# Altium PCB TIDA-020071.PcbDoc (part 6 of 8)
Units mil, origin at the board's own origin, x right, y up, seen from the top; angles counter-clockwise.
Board outline 5750 x 4050 mil, 6 copper layers (Top Layer, GND PLANE-1, SIGNAL LAYER, SIGNAL/POWER LAYER, GND PLANE-2, Bottom Layer), stack 59.616 mil thick; 776 components, 498 nets, 2205 pads, 871 vias.
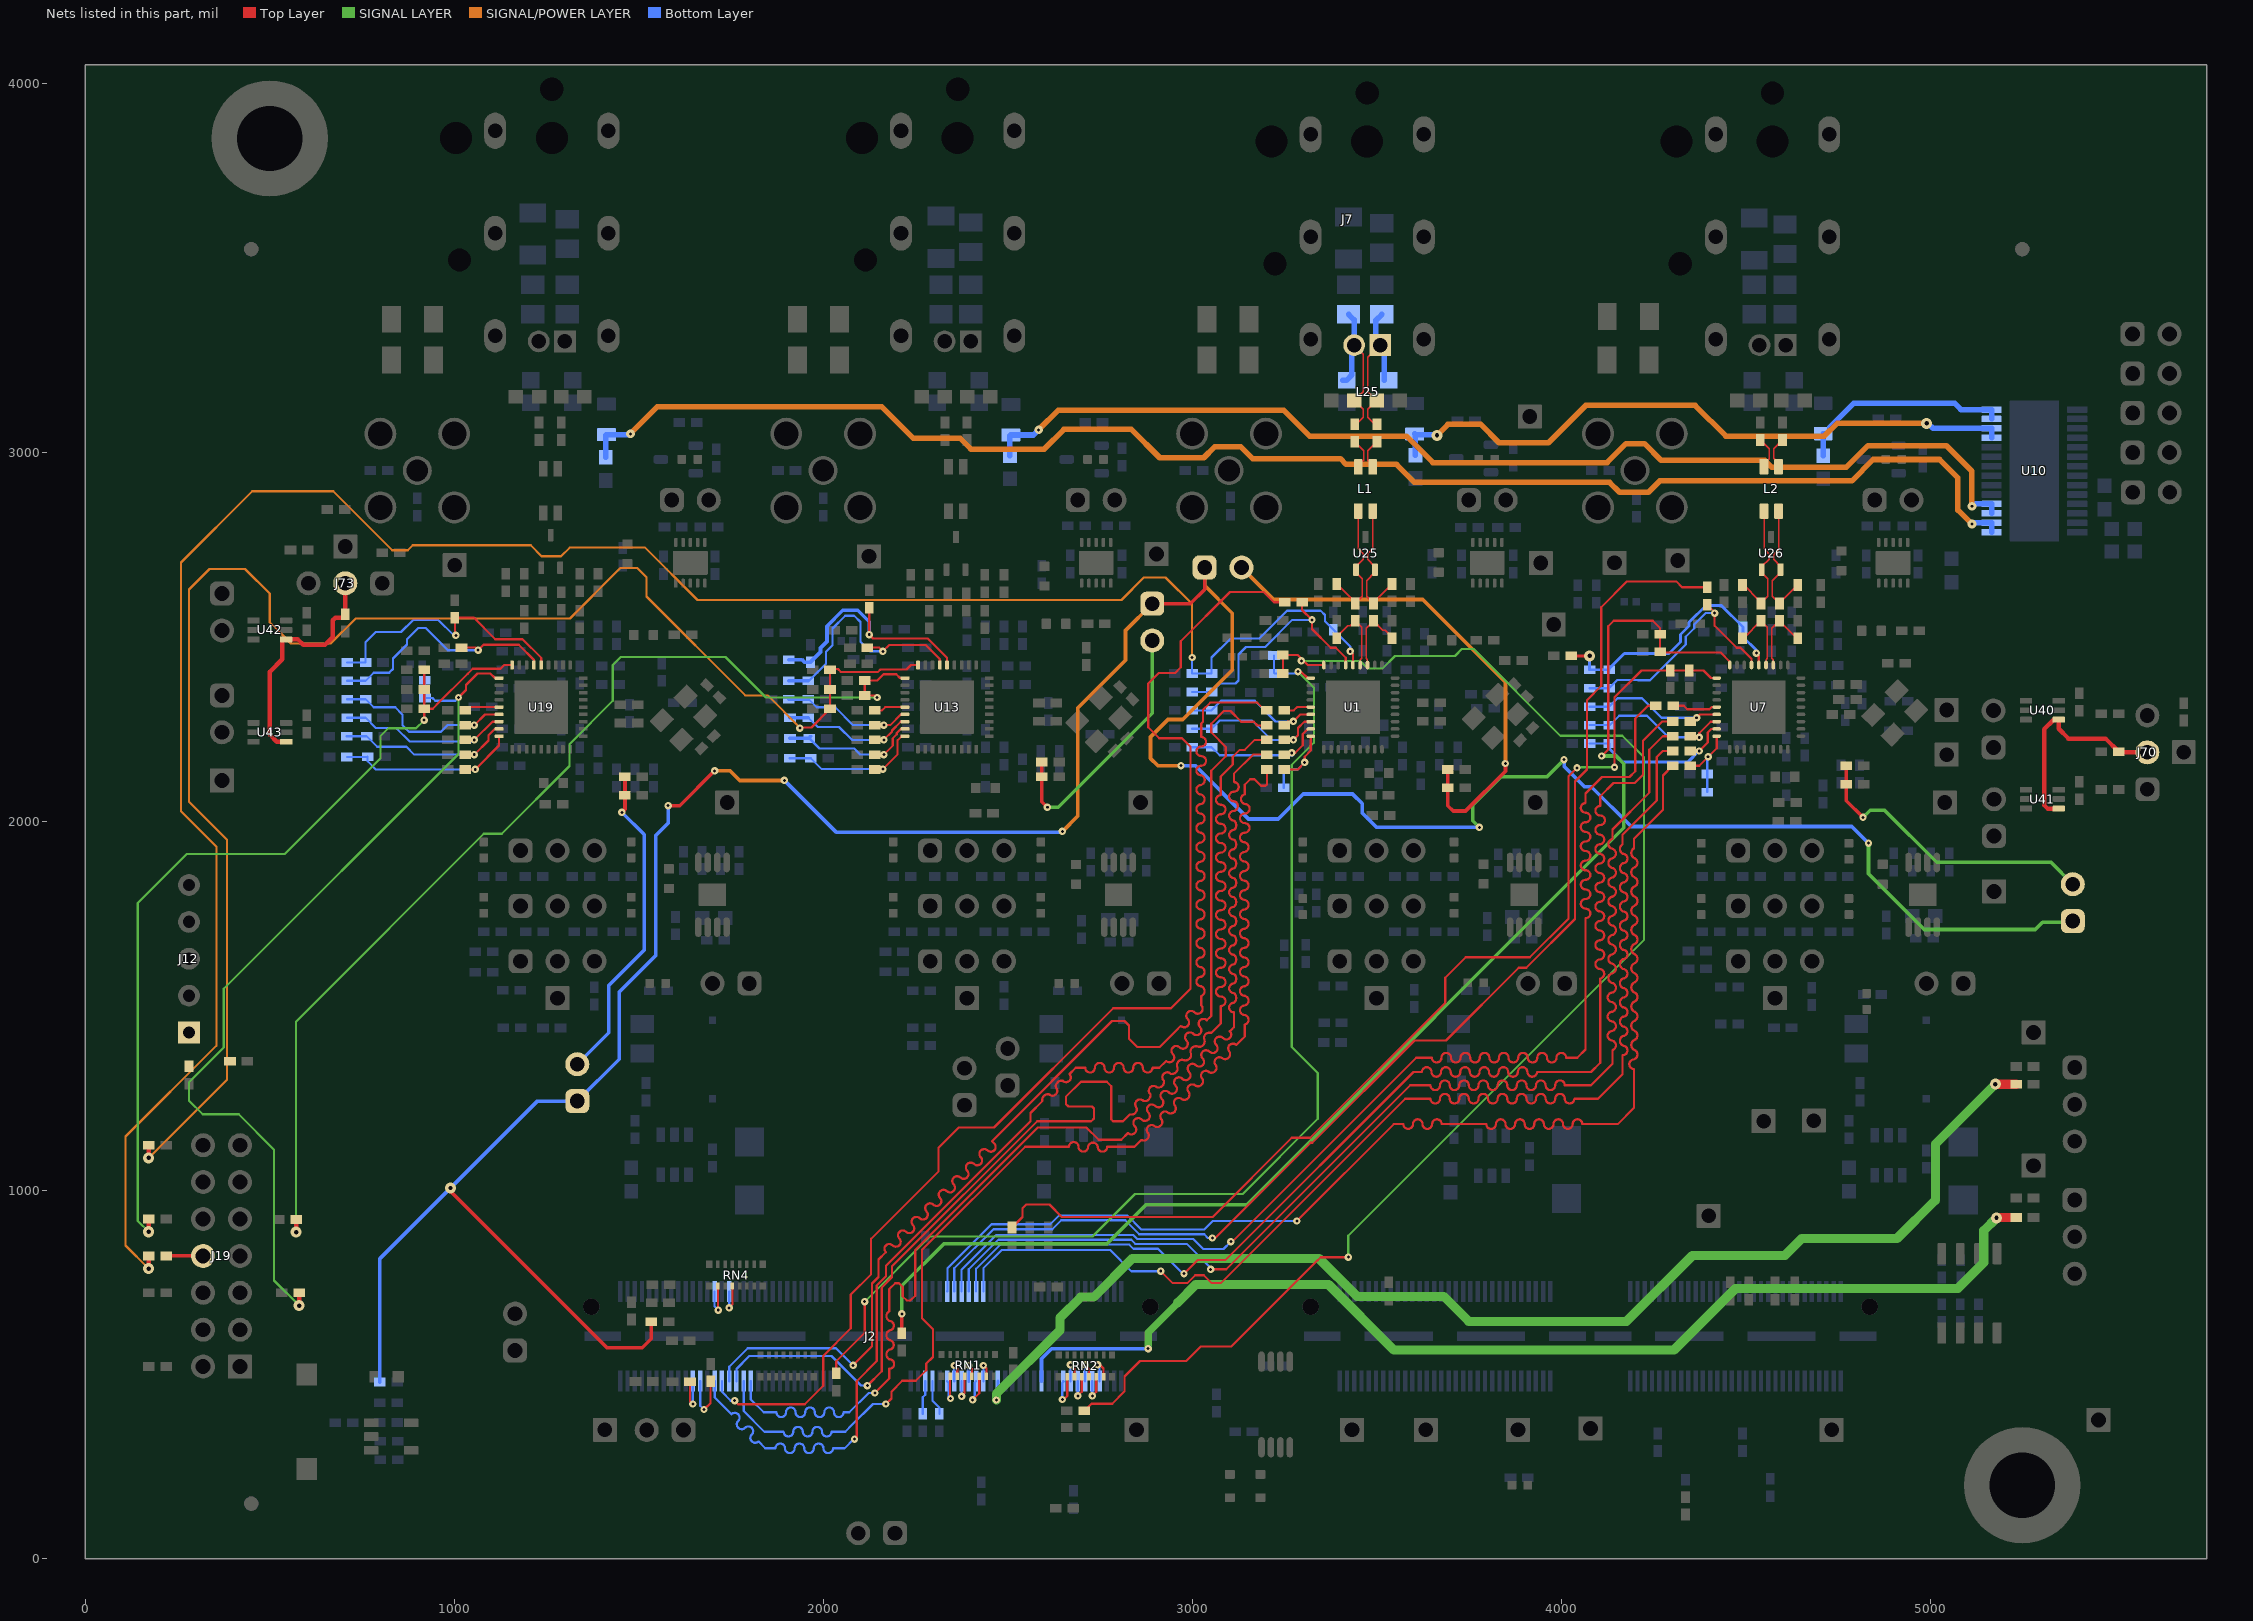
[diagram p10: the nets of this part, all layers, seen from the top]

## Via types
v1: diameter 20, hole 8, Top Layer to Bottom Layer, tented both sides, 637 vias
v2: diameter 30, hole 12, Top Layer to Bottom Layer, tented both sides, 105 vias
v3: diameter 19.68, hole 7.87, Top Layer to Bottom Layer, tented bottom, 68 vias
v4: diameter 19.68, hole 7.87, Top Layer to Bottom Layer, 25 vias
v5: diameter 24, hole 8, Top Layer to Bottom Layer, tented both sides, 24 vias
v6: diameter 19.68, hole 7.87, Top Layer to Bottom Layer, tented both sides, 12 vias

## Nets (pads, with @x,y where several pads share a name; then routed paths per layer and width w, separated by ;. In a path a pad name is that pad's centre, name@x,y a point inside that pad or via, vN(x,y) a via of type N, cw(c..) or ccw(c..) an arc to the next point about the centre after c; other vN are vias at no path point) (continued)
P0-R2-TD2: J2.89 RN4.12 | length 107.3
  Top Layer w6: v1(1745.28,680.75) 1754.01,689.48 RN4.12@1754.01,740
  Bottom Layer w6: v1(1745.28,680.75) J2.89@1745.28,725 J2.89@1745.28,725.2
P0-R2-TD3: J2.93 RN4.10 | length 120.3
  Top Layer w6: RN4.10@1714.64,740 1714.64,675.63 v1(1715.7,674.58)
  Bottom Layer w6: J2.93@1705.91,725 1705.91,684.37 v1(1715.7,674.58)
P1-R1-RCLK: J2.86 R52.2 | length 3530
  Top Layer w6: v1(2170,420) 2185,435 2185,453.4 2214.4,482.8 2250.8,482.8 2279.7,511.7 2279.7,529.7 2297.7,547.7 2297.7,622.8 2267.6,652.9 2267.6,837.34 2547.37,1117.11 2666.1,1117.11 cw(c2679.1,1117.11) 2692.1,1117.11 ccw(c2705.1,1117.11) 2718.1,1117.11 cw(c2731.1,1115.11) 2744.1,1117.11 ccw(c2757.1,1117.11) 2770.1,1117.11 2776.4,1117.11 2844.11,1117.11 2862.5,1135.49 ccw(c2868.67,1147.7) 2880.88,1153.88 cw(c2890.07,1163.07) 2899.26,1172.26 ccw(c2905.44,1184.47) 2917.65,1190.65 cw(c2926.84,1199.84) 2936.03,1209.03 ccw(c2942.21,1221.24) 2954.42,1227.42 cw(c2963.61,1236.61) 2972.8,1245.8 ccw(c2978.98,1258.01) 2991.19,1264.19 cw(c3000.38,1273.38) 3009.57,1282.57 ccw(c3015.75,1294.78) 3027.96,1300.96 cw(c3037.15,1310.15) 3046.34,1319.34 ccw(c3052.52,1331.55) 3064.73,1337.73 cw(c3073.92,1346.92) 3083.11,1356.11 ccw(c3089.29,1368.32) 3101.5,1374.5 cw(c3110.69,1383.69) 3119.88,1392.88 3135.4,1408.4 3142.7,1415.7 3142.7,1444.1 3142.7,1448.4 ccw(c3139.65,1461.4) 3142.7,1474.4 cw(c3142.7,1487.4) 3142.7,1500.4 ccw(c3139.65,1513.4) 3142.7,1526.4 cw(c3142.7,1539.4) 3142.7,1552.4 ccw(c3139.65,1565.4) 3142.7,1578.4 cw(c3142.7,1591.4) 3142.7,1604.4 ccw(c3139.65,1617.4) 3142.7,1630.4 cw(c3142.7,1643.4) 3142.7,1656.4 ccw(c3139.65,1669.4) 3142.7,1682.4 cw(c3142.7,1695.4) 3142.7,1708.4 ccw(c3139.65,1721.4) 3142.7,1734.4 cw(c3142.7,1747.4) 3142.7,1760.4 ccw(c3139.65,1773.4) 3142.7,1786.4 cw(c3142.7,1799.4) 3142.7,1812.4 ccw(c3139.65,1825.4) 3142.7,1838.4 cw(c3142.7,1851.4) 3142.7,1864.4 ccw(c3139.65,1877.4) 3142.7,1890.4 cw(c3142.7,1903.4) 3142.7,1916.4 ccw(c3139.65,1929.4) 3142.7,1942.4 cw(c3142.7,1955.4) 3142.7,1968.4 ccw(c3142.42,1981.4) 3142.7,1994.4 cw(c3142.7,2007.4) 3142.7,2020.4 ccw(c3142.7,2033.4) 3142.7,2046.4 cw(c3145.69,2059.4) 3142.7,2072.4 3142.7,2098.4 3157.5,2113.2 3169.1,2113.2 3186.8,2095.5 3199.1,2095.5 3202.76,2099.16 R52.2@3202.76,2140
  Bottom Layer w6: J2.86@1784.65,482.01 1784.65,401.15 1840.7,345.1 1866.9,345.1 1892.9,345.1 ccw(c1905.9,345.1) 1918.9,345.1 cw(c1931.9,345.1) 1944.9,345.1 ccw(c1957.9,345.1) 1970.9,345.1 cw(c1983.9,345.1) 1996.9,345.1 ccw(c2009.9,345.1) 2022.9,345.1 2048.9,345.1 2060,345.1 2078.38,363.48 2079.25,364.35 2134.9,420 v1(2170,420)
P1-R1-RCTL: J2.92 R53.2 | length 3411.1
  Top Layer w6: v1(1760,428.96) 1769.34,419.62 1950.03,419.62 2000,469.59 2000,550 2075,625 2075,716.94 2130,771.94 2130,868 2313,1051 2313,1115.11 2367.54,1169.66 2463.26,1169.66 2786.3,1492.7 2943,1492.7 2995.8,1545.5 2995.8,2201.37 2972.8,2224.36 2910.53,2224.36 2880.91,2253.98 2880.91,2372.57 2909.76,2401.42 2954.14,2401.42 2969.28,2416.56 2969.28,2487.37 3102.76,2620.85 3194.06,2620.85 3222,2592.91 R53.2@3250.76,2592.91
  Bottom Layer w6: J2.92@1725.59,482.01 1725.59,453 1749.63,428.96 v1(1760,428.96)
P1-R1-RD0: J2.84 R54.2 | length 3529.7
  Top Layer w6: v1(2140,450) 2179.4,489.4 2179.4,515.4 ccw(c2179.4,528.4) 2179.4,541.4 cw(c2186.24,554.4) 2179.4,567.4 ccw(c2178.25,580.4) 2179.4,593.4 cw(c2186.24,606.4) 2179.4,619.4 ccw(c2178.7,632.4) 2179.4,645.4 cw(c2186.24,658.4) 2179.4,671.4 2179.4,690.7 2179.4,731.5 2195.1,747.2 2205.7,747.2 2215.96,736.94 2215.96,711.14 2226.2,700.9 2236.8,700.9 2249.34,713.43 2249.34,837.46 2581.53,1169.66 2713.14,1169.66 2746.7,1136.1 2807.9,1136.1 2826.28,1154.48 ccw(c2835.48,1163.68) 2844.67,1172.87 cw(c2853.86,1182.06) 2863.05,1191.25 ccw(c2872.25,1200.45) 2881.44,1209.64 cw(c2890.63,1218.83) 2899.82,1228.02 ccw(c2909.02,1237.22) 2918.21,1246.41 cw(c2927.4,1255.6) 2936.59,1264.79 ccw(c2945.79,1273.99) 2954.98,1283.18 cw(c2964.17,1292.37) 2973.36,1301.56 ccw(c2982.56,1310.75) 2991.75,1319.95 cw(c3000.94,1329.14) 3010.13,1338.33 ccw(c3019.32,1347.52) 3028.52,1356.72 cw(c3037.71,1365.91) 3046.9,1375.1 ccw(c3056.09,1384.29) 3065.29,1393.49 cw(c3074.48,1402.68) 3083.67,1411.87 ccw(c3092.86,1421.06) 3102.06,1430.26 3107.05,1435.25 3113.2,1441.4 3113.2,1481.6 cw(c3113.2,1494.6) 3113.2,1507.6 ccw(c3103.45,1520.6) 3113.2,1533.6 cw(c3113.2,1546.6) 3113.2,1559.6 ccw(c3103.45,1572.6) 3113.2,1585.6 cw(c3113.2,1598.6) 3113.2,1611.6 ccw(c3103.45,1624.6) 3113.2,1637.6 cw(c3113.2,1650.6) 3113.2,1663.6 ccw(c3103.45,1676.6) 3113.2,1689.6 cw(c3113.2,1702.6) 3113.2,1715.6 ccw(c3103.45,1728.6) 3113.2,1741.6 cw(c3113.2,1754.6) 3113.2,1767.6 ccw(c3103.45,1780.6) 3113.2,1793.6 cw(c3113.2,1806.6) 3113.2,1819.6 ccw(c3103.45,1832.6) 3113.2,1845.6 cw(c3113.2,1858.6) 3113.2,1871.6 ccw(c3103.45,1884.6) 3113.2,1897.6 cw(c3113.2,1910.6) 3113.2,1923.6 ccw(c3103.45,1936.6) 3113.2,1949.6 cw(c3113.2,1962.6) 3113.2,1975.6 ccw(c3103.45,1988.6) 3113.2,2001.6 cw(c3113.2,2014.6) 3113.2,2027.6 ccw(c3110.91,2040.6) 3113.2,2053.6 cw(c3113.2,2066.6) 3113.2,2079.6 ccw(c3113.2,2092.6) 3113.2,2105.6 3113.2,2121.7 3113.2,2128.4 3164.8,2180 R54.2@3202.76,2180
  Bottom Layer w6: J2.84@1804.33,482.01 1804.02,481.69 1804.02,432.43 1838.75,397.7 1847.3,397.7 1873.3,397.7 ccw(c1886.3,397.7) 1899.3,397.7 cw(c1912.3,397.7) 1925.3,397.7 ccw(c1938.3,397.7) 1951.3,397.7 cw(c1964.3,397.7) 1977.3,397.7 ccw(c1990.3,397.7) 2003.3,397.7 cw(c2016.3,397.7) 2029.3,397.7 ccw(c2042.3,397.7) 2055.3,397.7 2071.1,397.7 2123.4,450 v1(2140,450)
P1-R1-RD1: J2.88 R55.2 | length 3536.2
  Top Layer w6: v1(2120,470) 2158.55,508.55 2158.55,735.91 2186.74,764.1 2186.74,793.25 2580,1186.51 2726.31,1186.51 2733.9,1194.1 2733.9,1221 2728.8,1226.1 2664.78,1226.1 2657.8,1233.08 2657.8,1252.7 2698.8,1293.7 2768.4,1293.7 2780.7,1281.4 2780.7,1191.6 2785.79,1186.51 2812.81,1186.51 2831.2,1204.9 ccw(c2835.34,1219.14) 2849.58,1223.28 cw(c2858.78,1232.48) 2867.97,1241.67 ccw(c2872.11,1255.91) 2886.35,1260.05 cw(c2895.55,1269.24) 2904.74,1278.44 ccw(c2908.88,1292.68) 2923.12,1296.82 cw(c2932.32,1306.01) 2941.51,1315.21 ccw(c2945.65,1329.45) 2959.89,1333.59 cw(c2973.06,1338.81) 2978.28,1351.98 ccw(c2982.42,1366.22) 2996.66,1370.36 cw(c3009.83,1375.58) 3015.05,1388.75 ccw(c3019.19,1402.99) 3033.43,1407.13 cw(c3046.6,1412.35) 3051.82,1425.52 3068.1,1441.8 3077.5,1451.2 3077.5,1467.8 3077.5,1472.44 3077.5,1498.44 ccw(c3077.5,1511.44) 3077.5,1524.44 cw(c3077.9,1537.44) 3077.5,1550.44 ccw(c3077.5,1563.44) 3077.5,1576.44 cw(c3077.9,1589.44) 3077.5,1602.44 ccw(c3077.5,1615.44) 3077.5,1628.44 cw(c3077.9,1641.44) 3077.5,1654.44 ccw(c3077.5,1667.44) 3077.5,1680.44 cw(c3077.9,1693.44) 3077.5,1706.44 ccw(c3077.5,1719.44) 3077.5,1732.44 cw(c3077.9,1745.44) 3077.5,1758.44 ccw(c3077.5,1771.44) 3077.5,1784.44 cw(c3077.9,1797.44) 3077.5,1810.44 ccw(c3077.5,1823.44) 3077.5,1836.44 cw(c3077.9,1849.44) 3077.5,1862.44 ccw(c3077.5,1875.44) 3077.5,1888.44 cw(c3077.9,1901.44) 3077.5,1914.44 ccw(c3077.5,1927.44) 3077.5,1940.44 cw(c3077.9,1953.44) 3077.5,1966.44 ccw(c3077.5,1979.44) 3077.5,1992.44 cw(c3077.9,2005.44) 3077.5,2018.44 ccw(c3077.5,2031.44) 3077.5,2044.44 cw(c3077.9,2057.44) 3077.5,2070.44 3077.5,2096.44 3077.5,2120.8 3110,2153.3 3110,2174.2 3128.7,2192.9 3143,2192.9 3170.1,2220 R55.2@3202.76,2220
  Bottom Layer w6: J2.88@1764.96,482.01 1764.96,514.96 1800,550 2022.36,550 2102.36,470 v1(2120,470)
P1-R1-RD2: J2.94 R56.2 | length 3555.4
  Top Layer w6: v1(2085,325) 2090.97,330.97 2090.97,481.97 2145.55,536.55 2145.55,741.3 2170,765.74 2170,795.62 2170.72,795.62 2561.8,1186.7 2561.8,1208.8 2593.95,1240.95 cw(c2609.46,1243.82) 2612.33,1259.33 ccw(c2621.53,1268.53) 2630.72,1277.72 cw(c2646.23,1280.59) 2649.1,1296.1 ccw(c2658.3,1305.3) 2667.49,1314.49 2684.4,1331.4 2710.4,1331.4 ccw(c2723.4,1331.4) 2736.4,1331.4 cw(c2749.4,1331.4) 2762.4,1331.4 ccw(c2775.4,1331.4) 2788.4,1331.4 cw(c2801.4,1331.4) 2814.4,1331.4 ccw(c2827.4,1331.4) 2840.4,1331.4 cw(c2853.4,1331.4) 2866.4,1331.4 ccw(c2879.4,1331.4) 2892.4,1331.4 2911.2,1331.4 2929.58,1349.78 ccw(c2938.49,1359.26) 2947.97,1368.17 cw(c2957.16,1377.36) 2966.35,1386.55 ccw(c2975.26,1396.03) 2984.74,1404.94 cw(c2993.93,1414.13) 3003.12,1423.32 ccw(c3012.03,1432.8) 3021.51,1441.71 cw(c3030.7,1450.9) 3039.89,1460.09 3049.6,1469.8 3051.9,1472.1 3051.9,2136.5 3091.3,2175.9 3091.3,2200.9 3051.9,2240.3 3051.9,2263.9 3086,2298 3104.2,2298 3133,2269.2 3167.1,2269.2 3177.3,2259 3201.76,2259 R56.2@3202.76,2260
  Bottom Layer w6: J2.94@1705.91,482.01 1706.22,481.69 1706.22,437.47 1751.35,392.35 cw(c1760.54,383.15) 1769.73,373.96 ccw(c1778.92,364.77) 1788.12,355.58 cw(c1797.31,346.39) 1806.5,337.19 ccw(c1815.69,328) 1824.89,318.81 1843.27,300.42 1843.7,300 1870.7,300 cw(c1883.7,300) 1896.7,300 ccw(c1909.7,300) 1922.7,300 cw(c1935.7,300) 1948.7,300 ccw(c1961.7,300) 1974.7,300 cw(c1987.7,300) 2000.7,300 ccw(c2013.7,300) 2026.7,300 2052.7,300 2058.24,300 2083.24,325 v1(2085,325)
P1-R1-RD3: J2.90 R57.2 | length 3562.5
  Top Layer w6: v1(2081.12,525) 2132.55,576.43 2132.55,746.68 2150,764.13 2150,811.42 2170,831.42 cw(c2179.19,840.61) 2188.38,849.8 ccw(c2197.08,859.49) 2206.77,868.19 cw(c2215.96,877.38) 2225.15,886.57 ccw(c2233.85,896.26) 2243.54,904.96 cw(c2252.73,914.15) 2261.92,923.34 ccw(c2270.62,933.03) 2280.31,941.73 cw(c2289.5,950.92) 2298.69,960.11 ccw(c2307.39,969.8) 2317.08,978.5 cw(c2326.27,987.69) 2335.46,996.88 ccw(c2344.16,1006.57) 2353.85,1015.26 cw(c2363.04,1024.46) 2372.23,1033.65 ccw(c2380.93,1043.34) 2390.62,1052.03 cw(c2399.81,1061.23) 2409,1070.42 ccw(c2417.7,1080.11) 2427.39,1088.8 cw(c2436.58,1098) 2445.77,1107.19 ccw(c2454.46,1116.88) 2464.16,1125.57 2457.34,1132.39 2782.85,1457.9 2817,1457.9 2828.8,1446.1 2828.8,1410 2851,1387.8 2912.49,1387.8 2956.89,1432.21 2969.55,1444.86 ccw(c2978.74,1454.05) 2987.93,1463.24 cw(c2997.12,1472.44) 3006.32,1481.63 ccw(c3015.51,1490.82) 3024.7,1500.01 3024.7,1526.01 ccw(c3019.81,1539.01) 3024.7,1552.01 cw(c3024.7,1565.01) 3024.7,1578.01 ccw(c3019.81,1591.01) 3024.7,1604.01 cw(c3024.7,1617.01) 3024.7,1630.01 ccw(c3019.81,1643.01) 3024.7,1656.01 cw(c3024.7,1669.01) 3024.7,1682.01 ccw(c3019.81,1695.01) 3024.7,1708.01 cw(c3024.7,1721.01) 3024.7,1734.01 ccw(c3019.81,1747.01) 3024.7,1760.01 cw(c3024.7,1773.01) 3024.7,1786.01 ccw(c3019.81,1799.01) 3024.7,1812.01 cw(c3024.7,1825.01) 3024.7,1838.01 ccw(c3019.81,1851.01) 3024.7,1864.01 cw(c3024.7,1877.01) 3024.7,1890.01 ccw(c3019.81,1903.01) 3024.7,1916.01 cw(c3024.7,1929.01) 3024.7,1942.01 ccw(c3019.81,1955.01) 3024.7,1968.01 cw(c3024.7,1981.01) 3024.7,1994.01 ccw(c3019.81,2007.01) 3024.7,2020.01 cw(c3024.7,2033.01) 3024.7,2046.01 ccw(c3019.81,2059.01) 3024.7,2072.01 cw(c3024.7,2085.01) 3024.7,2098.01 ccw(c3020.62,2111.01) 3024.7,2124.01 cw(c3024.7,2137.01) 3024.7,2150.01 ccw(c3024.7,2163.01) 3024.7,2176.01 cw(c3024.7,2189.01) 3024.7,2202.01 ccw(c3024.7,2215.01) 3024.7,2228.01 3024.7,2254.01 3024.7,2264.2 3029.6,2269.1 3029.6,2301.5 3049.1,2321 3176.5,2321 3197.5,2300 R57.2@3202.76,2300
  Bottom Layer w6: J2.90@1745.28,482.01 1745.28,521.15 1795.43,571.3 2034.81,571.3 v1(2081.12,525)
P1-R1-TCLK: J2.48 RN1.3 | length 75.1
  Top Layer w6: v1(2355.51,524.52) 2363.73,516.3 RN1.3@2363.73,495.33
  Bottom Layer w6: J2.48@2355.51,482.01 v1(2355.51,524.52)
P1-R1-TCTL: J2.44 RN1.5 | length 77.5
  Top Layer w6: v1(2394.88,524.52) 2403.1,516.3 RN1.5@2403.1,495.33
  Bottom Layer w6: J2.44@2394.88,479.61 J2.44@2394.88,482.01 v1(2394.88,524.52)
P1-R1-TD0: J2.42 RN1.6 | length 126.1
  Top Layer w6: v1(2405.1,431.25) 2422.79,448.94 RN1.6@2422.79,495.33
  Bottom Layer w6: v1(2405.1,431.25) 2410.89,437.03 2410.89,478.26 J2.42@2414.57,482.01
P1-R1-TD1: J2.50 RN1.2 | length 111.5
  Top Layer w6: RN1.2@2344.05,495.33 2344.05,435.95 v1(2345,435)
  Bottom Layer w6: J2.50@2335.83,482.01 2339.51,478.33 2339.51,440.49 v1(2345,435)
P1-R1-TD2: J2.46 RN1.4 | length 99.3
  Top Layer w6: v1(2375.2,440.72) 2383.42,448.94 RN1.4@2383.42,495.33
  Bottom Layer w6: v1(2375.2,440.72) J2.46@2375.2,482.01
P1-R1-TD3: J2.40 RN1.7 | length 75.1
  Top Layer w6: v1(2434.25,524.52) 2442.47,516.3 RN1.7@2442.47,495.33
  Bottom Layer w6: J2.40@2434.25,482.01 v1(2434.25,524.52)
P1-R2-RCLK: J2.49 R105.2 | length 3481.1
  Top Layer w6: v1(3283.89,916.05) 3546.43,1178.6 3572.43,1178.6 ccw(c3585.43,1178.6) 3598.43,1178.6 cw(c3611.43,1178.6) 3624.43,1178.6 ccw(c3637.43,1178.6) 3650.43,1178.6 cw(c3663.43,1178.6) 3676.43,1178.6 3700.9,1178.6 3771.3,1178.6 3797.3,1178.6 ccw(c3810.3,1178.6) 3823.3,1178.6 cw(c3836.3,1178.6) 3849.3,1178.6 ccw(c3862.3,1178.6) 3875.3,1178.6 cw(c3888.3,1178.6) 3901.3,1178.6 ccw(c3914.3,1178.6) 3927.3,1178.6 cw(c3940.3,1178.6) 3953.3,1178.6 ccw(c3966.3,1178.6) 3979.3,1178.6 cw(c3992.3,1178.6) 4005.3,1178.6 ccw(c4018.3,1178.6) 4031.3,1178.6 cw(c4044.3,1178.6) 4057.3,1178.6 4063.49,1178.6 4153.5,1178.6 4197.7,1222.8 4197.7,1292.67 4197.7,1302.09 4197.7,1328.09 cw(c4197.7,1341.09) 4197.7,1354.09 ccw(c4193.27,1367.09) 4197.7,1380.09 cw(c4204.97,1393.09) 4197.7,1406.09 ccw(c4193.27,1419.09) 4197.7,1432.09 cw(c4204.97,1445.09) 4197.7,1458.09 ccw(c4193.27,1471.09) 4197.7,1484.09 cw(c4204.97,1497.09) 4197.7,1510.09 ccw(c4193.27,1523.09) 4197.7,1536.09 cw(c4204.97,1549.09) 4197.7,1562.09 ccw(c4193.27,1575.09) 4197.7,1588.09 cw(c4204.97,1601.09) 4197.7,1614.09 ccw(c4193.27,1627.09) 4197.7,1640.09 cw(c4204.97,1653.09) 4197.7,1666.09 ccw(c4193.27,1679.09) 4197.7,1692.09 cw(c4204.97,1705.09) 4197.7,1718.09 ccw(c4193.27,1731.09) 4197.7,1744.09 cw(c4204.97,1757.09) 4197.7,1770.09 ccw(c4193.27,1783.09) 4197.7,1796.09 cw(c4204.97,1809.09) 4197.7,1822.09 ccw(c4193.27,1835.09) 4197.7,1848.09 cw(c4204.97,1861.09) 4197.7,1874.09 ccw(c4193.27,1887.09) 4197.7,1900.09 cw(c4204.97,1913.09) 4197.7,1926.09 4197.7,1952.09 4276.04,2030.43 4276.04,2123.28 R105.2@4302.76,2150
  Bottom Layer w6: J2.49@2335.83,725 2337.28,726.46 2337.28,787.97 2456.27,906.96 2615.75,906.96 2640.09,931.3 2824.01,931.3 2862.23,893.08 3033.08,893.08 3056.06,916.05 v1(3283.89,916.05) v1@3283.89,914.96
P1-R2-RCTL: J2.47 R106.2 | length 3374.4
  Top Layer w6: v1(3055,870) 3062.76,870 3321.16,1128.4 3325.68,1128.4 3602.79,1405.51 3687.98,1405.51 3884.96,1602.48 3905.58,1602.48 4037.6,1734.5 4037.6,2107.1 4070,2139.5 4070,2327.71 4108.91,2366.62 4108.91,2495.32 4108.91,2579.78 4178.73,2649.6 4311.8,2649.6 4327.78,2633.62 R106.2@4395.94,2633.62
  Bottom Layer w6: J2.47@2355.51,725 2355.51,787.81 2461.66,893.96 2621.13,893.96 2645.47,918.3 2818.62,918.3 2856.92,880 3032.63,880 3042.63,870 v1(3055,870)
P1-R2-RD0: J2.39 R107.2 | length 3492.3
  Top Layer w6: v1(2915,780) 2947.3,747.7 2987.1,747.7 3008.5,769.1 3031.5,769.1 3052.9,747.7 3077.7,747.7 3577.51,1247.51 3620,1247.51 3646,1247.51 ccw(c3659,1247.51) 3672,1247.51 cw(c3685,1247.51) 3698,1247.51 ccw(c3711,1247.51) 3724,1247.51 cw(c3737,1247.51) 3750,1247.51 ccw(c3763,1247.51) 3776,1247.51 cw(c3789,1247.51) 3802,1247.51 ccw(c3815,1247.51) 3828,1247.51 cw(c3841,1247.51) 3854,1247.51 ccw(c3867,1247.51) 3880,1247.51 cw(c3893,1247.51) 3906,1247.51 ccw(c3919,1247.51) 3932,1247.51 cw(c3945,1247.51) 3958,1247.51 ccw(c3971,1247.51) 3984,1247.51 cw(c3997,1247.51) 4010,1247.51 ccw(c4023,1247.51) 4036,1247.51 4060.6,1247.51 4100.11,1247.51 4166.8,1314.2 4166.8,1358.1 4166.8,1365.42 ccw(c4166.8,1378.42) 4166.8,1391.42 cw(c4175.28,1404.42) 4166.8,1417.42 ccw(c4166.8,1430.42) 4166.8,1443.42 cw(c4175.28,1456.42) 4166.8,1469.42 ccw(c4166.8,1482.42) 4166.8,1495.42 cw(c4175.28,1508.42) 4166.8,1521.42 ccw(c4166.8,1534.42) 4166.8,1547.42 cw(c4175.28,1560.42) 4166.8,1573.42 ccw(c4166.8,1586.42) 4166.8,1599.42 cw(c4175.28,1612.42) 4166.8,1625.42 ccw(c4166.8,1638.42) 4166.8,1651.42 cw(c4175.28,1664.42) 4166.8,1677.42 ccw(c4166.8,1690.42) 4166.8,1703.42 cw(c4175.28,1716.42) 4166.8,1729.42 ccw(c4166.8,1742.42) 4166.8,1755.42 cw(c4175.28,1768.42) 4166.8,1781.42 ccw(c4166.8,1794.42) 4166.8,1807.42 cw(c4175.28,1820.42) 4166.8,1833.42 ccw(c4166.8,1846.42) 4166.8,1859.42 cw(c4175.28,1872.42) 4166.8,1885.42 ccw(c4166.8,1898.42) 4166.8,1911.42 cw(c4175.28,1924.42) 4166.8,1937.42 4166.8,1963.42 4259,2055.62 4259,2173.5 4275.5,2190 R107.2@4302.76,2190
  Bottom Layer w6: J2.39@2434.25,725 2434.25,787.88 2483.68,837.32 2778.08,837.32 2835.4,780 v1(2915,780)
P1-R2-RD1: J2.43 R108.2 | length 3508.8
  Top Layer w6: v1(3050,785) 3092.28,785 3591.22,1283.93 3620,1283.93 3646,1283.93 ccw(c3659,1283.93) 3672,1283.93 cw(c3685,1283.93) 3698,1283.93 ccw(c3711,1283.93) 3724,1283.93 cw(c3737,1283.93) 3750,1283.93 ccw(c3763,1283.93) 3776,1283.93 cw(c3789,1283.93) 3802,1283.93 ccw(c3815,1283.93) 3828,1283.93 cw(c3841,1283.93) 3854,1283.93 ccw(c3867,1283.93) 3880,1283.93 cw(c3893,1283.93) 3906,1283.93 ccw(c3919,1283.93) 3932,1283.93 cw(c3945,1283.93) 3958,1283.93 ccw(c3971,1283.93) 3984,1283.93 cw(c3997,1283.93) 4010,1283.93 4035.1,1283.93 4080.97,1283.93 4139.1,1342.06 4139.1,1370.7 4139.1,1379.1 ccw(c4134.96,1392.1) 4139.1,1405.1 cw(c4139.1,1418.1) 4139.1,1431.1 ccw(c4134.96,1444.1) 4139.1,1457.1 cw(c4139.1,1470.1) 4139.1,1483.1 ccw(c4134.96,1496.1) 4139.1,1509.1 cw(c4139.1,1522.1) 4139.1,1535.1 ccw(c4134.96,1548.1) 4139.1,1561.1 cw(c4141.31,1574.1) 4139.1,1587.1 ccw(c4134.96,1600.1) 4139.1,1613.1 cw(c4141.31,1626.1) 4139.1,1639.1 ccw(c4134.96,1652.1) 4139.1,1665.1 cw(c4141.31,1678.1) 4139.1,1691.1 ccw(c4134.96,1704.1) 4139.1,1717.1 cw(c4141.31,1730.1) 4139.1,1743.1 ccw(c4134.96,1756.1) 4139.1,1769.1 cw(c4141.31,1782.1) 4139.1,1795.1 ccw(c4134.96,1808.1) 4139.1,1821.1 cw(c4141.31,1834.1) 4139.1,1847.1 ccw(c4134.96,1860.1) 4139.1,1873.1 cw(c4141.31,1886.1) 4139.1,1899.1 ccw(c4134.96,1912.1) 4139.1,1925.1 cw(c4141.31,1938.1) 4139.1,1951.1 4139.1,1977.1 4239,2077 4239,2193.2 4275.8,2230 R108.2@4302.76,2230
  Bottom Layer w6: J2.43@2394.88,725 2394.88,785.28 2474.9,865.3 2834.85,865.3 2846.15,854 2985.36,854 3050,789.36 v1(3050,785)
P1-R2-RD2: J2.41 R109.2 | length 3525.3
  Top Layer w6: v1(2978.12,773.3) 3014.82,810 3090,810 3600,1320 3622.66,1320 cw(c3635.66,1320) 3648.66,1320 ccw(c3661.66,1320) 3674.66,1320 cw(c3687.66,1320) 3700.66,1320 ccw(c3713.66,1320) 3726.66,1320 cw(c3739.66,1320) 3752.66,1320 ccw(c3765.66,1320) 3778.66,1320 cw(c3791.66,1320) 3804.66,1320 ccw(c3817.66,1320) 3830.66,1320 cw(c3843.66,1320) 3856.66,1320 ccw(c3869.66,1320) 3882.66,1320 cw(c3895.66,1320) 3908.66,1320 ccw(c3921.66,1320) 3934.66,1320 3960,1320 4080.97,1320 4106,1345.03 4106,1567.9 4106,1573.1 ccw(c4103.82,1586.1) 4106,1599.1 cw(c4106,1612.1) 4106,1625.1 ccw(c4103.82,1638.1) 4106,1651.1 cw(c4106,1664.1) 4106,1677.1 ccw(c4103.82,1690.1) 4106,1703.1 cw(c4106,1716.1) 4106,1729.1 ccw(c4103.82,1742.1) 4106,1755.1 cw(c4106,1768.1) 4106,1781.1 ccw(c4103.82,1794.1) 4106,1807.1 cw(c4106,1820.1) 4106,1833.1 ccw(c4103.82,1846.1) 4106,1859.1 cw(c4106,1872.1) 4106,1885.1 ccw(c4103.82,1898.1) 4106,1911.1 cw(c4106,1924.1) 4106,1937.1 ccw(c4103.82,1950.1) 4106,1963.1 cw(c4106,1976.1) 4106,1989.1 ccw(c4106,2002.1) 4106,2015.1 cw(c4106,2028.1) 4106,2041.1 4106,2067.1 4142.1,2103.2 4200,2103.2 4222,2125.2 4222,2217.8 4274.2,2270 R109.2@4302.76,2270
  Bottom Layer w6: J2.41@2414.57,725 2414.57,786.58 2479.98,852 2829.77,852 2840.77,841 2907.66,841 2978.12,770.54 v1(2978.12,773.3)
P1-R2-RD3: J2.45 R110.2 | length 3481.2
  Top Layer w6: v1(3105,860) 3108.98,860 3607.68,1358.7 3623.62,1358.7 3649.62,1358.7 ccw(c3662.62,1358.7) 3675.62,1358.7 cw(c3688.62,1358.7) 3701.62,1358.7 ccw(c3714.62,1358.7) 3727.62,1358.7 cw(c3740.62,1358.7) 3753.62,1358.7 ccw(c3766.62,1358.7) 3779.62,1358.7 cw(c3792.62,1358.7) 3805.62,1358.7 ccw(c3818.62,1358.7) 3831.62,1358.7 cw(c3844.62,1358.7) 3857.62,1358.7 ccw(c3870.62,1358.7) 3883.62,1358.7 cw(c3896.62,1358.7) 3909.62,1358.7 ccw(c3922.62,1358.7) 3935.62,1358.7 cw(c3948.62,1358.7) 3961.62,1358.7 ccw(c3974.62,1358.7) 3987.62,1358.7 cw(c4000.62,1358.7) 4013.62,1358.7 4026,1358.7 4044,1358.7 4066.3,1381 4066.3,1712.1 4066.3,1736.7 ccw(c4066.3,1749.7) 4066.3,1762.7 cw(c4066.3,1775.7) 4066.3,1788.7 ccw(c4066.3,1801.7) 4066.3,1814.7 cw(c4066.3,1827.7) 4066.3,1840.7 ccw(c4066.3,1853.7) 4066.3,1866.7 cw(c4066.3,1879.7) 4066.3,1892.7 ccw(c4066.3,1905.7) 4066.3,1918.7 cw(c4066.3,1931.7) 4066.3,1944.7 ccw(c4066.3,1957.7) 4066.3,1970.7 cw(c4066.3,1983.7) 4066.3,1996.7 ccw(c4066.3,2009.7) 4066.3,2022.7 cw(c4066.3,2035.7) 4066.3,2048.7 4066.3,2074.7 4110.9,2119.3 4185.3,2119.3 4201,2135 4201,2278 4235.5,2312.5 R110.2@4256.58,2312.5
  Bottom Layer w6: J2.45@2375.2,725 2375.2,783.98 2469.51,878.3 2840.24,878.3 2851.54,867 3003,867 3030,840 3085,840 v1(3105,860)
P1-R2-TCLK: J2.12 RN2.5 | length 81.8
  Top Layer w6: v1(2710,526.31) 2720.67,515.63 RN2.5@2720.67,494.09
  Bottom Layer w6: J2.12@2709.84,482.01 2709.84,526.57 2710,526.73 v1(2710,526.31)
P1-R2-TCTL: J2.8 RN2.7 | length 100.9
  Top Layer w6: v1(2743.82,526.31) 2743.82,527.51 2746.31,530 2760.04,516.26 RN2.7@2760.04,494.09
  Bottom Layer w6: v1(2743.82,526.31) 2743.82,527.08 2746.73,530 2750,526.73 2749.21,525.94 J2.8@2749.21,482.01
P1-R2-TD0: J2.14 RN2.4 | length 96.2
  Top Layer w6: v1(2690.16,442.18) 2700.99,453.01 RN2.4@2700.99,494.09
  Bottom Layer w6: v1(2690.16,442.18) J2.14@2690.16,482.01
P1-R2-TD1: J2.18 RN2.2 | length 121.2
  Top Layer w6: v1(2648.16,432.43) 2652.01,432.43 2661.62,442.04 RN2.2@2661.62,494.09
  Bottom Layer w6: v1(2648.16,432.43) 2648.16,476.94 2652.01,480.79 J2.18@2650.79,482.01
P1-R2-TD2: J2.16 RN2.3 | length 82.2
  Top Layer w6: v1(2670,526.31) 2681.3,515 RN2.3@2681.3,494.09
  Bottom Layer w6: v1(2670,526.31) 2670,526.73 2670.47,526.26 J2.16@2670.47,482.01
P1-R2-TD3: J2.10 RN2.6 | length 96.2
  Top Layer w6: v1(2729.53,442.18) 2740.36,453.01 RN2.6@2740.36,494.09
  Bottom Layer w6: v1(2729.53,442.18) J2.10@2729.53,482.01
Pin18_2: R363.1 R374.1 R375.2 U7.18 | length 3628.8
  Top Layer w6: v1(4110,2176.14) 4127.62,2193.76 4127.62,2357.62 4127.62,2505.66 4127.62,2528.16 4142.53,2543.07 4248.13,2543.07 4268.43,2522.77 R374.1@4268.43,2505.94 R375.2@4268.43,2458.7 4270.6,2456.53 4340.8,2456.53 4432.6,2456.53 4457.09,2432.04 U7.18@4457.09,2422.91
  Top Layer w10: R363.1@2213.11,612.29 v1(2213.11,664.5)
  SIGNAL LAYER w10: v1(2213.11,664.5) 2213.11,740.31 2327.3,854.5 2769.5,854.5 2875,960 3148.4,960 4170,1981.6 4170,2155 4148.86,2176.14 v1(4110,2176.14)
Pin18_3: R279.2 R382.1 R383.2 R412.1 U13.18 | length 4267.2
  Top Layer w6: v1@1936.68,2253.81 1968.18,2253.81 R382.1@2018.62,2304.25 R383.2@2018.62,2356.65 R279.2@2018.62,2410 2020.76,2412.14 2039.99,2412.14 2047.87,2404.25 2148.95,2404.25 2155.58,2410.88 2225.88,2410.88 2237.91,2422.91 U13.18@2257.09,2422.91
  Top Layer w12: v2(171.91,1086.89) R412.1@171.91,1121.45
  SIGNAL/POWER LAYER w6: v2(171.91,1086.89) 384.17,1299.15 384.17,1949.25 281.23,2052.19 281.23,2627.83 336.63,2683.23 433.35,2683.23 499.95,2616.63 499.95,2538.75 557.5,2481.2 665,2481.2 733.02,2549.22 1313.63,2549.22 1450.55,2686.13 1495.6,2686.13 1521.12,2660.62 1521.12,2608.43 1788.94,2340.61 1849.89,2340.61 v1@1936.68,2253.81
  other v1: 1936.68,2251.81
Pin18_4: R281.2 R390.1 R391.2 R417.1 U19.18 | length 2378.4
  Top Layer w6: v1(918.62,2273.54) R390.1@918.62,2304.25 ; R391.2@918.62,2410 R281.2@918.62,2356.65 R390.1@918.62,2304.25 ; U19.18@1157.09,2422.91 1135.38,2422.91 1125.46,2413 1050.5,2413 1036.82,2399.32 1036.75,2399.39 953.05,2315.69 953.05,2315.55 941.75,2304.25 R390.1@918.62,2304.25
  Top Layer w12: v2(171.91,886.89) R417.1@171.91,921.45
  SIGNAL LAYER w6: v2(171.91,886.89) 142.7,916.1 142.7,1778 275.15,1910.45 540.65,1910.45 800,2169.8 800,2230 821.7,2251.7 896.78,2251.7 v1(918.62,2273.54)
Pin19_2: R364.2 R372.1 R373.2 U7.19 | length 2962.4
  Top Layer w6: R364.2@2511.62,898.3 2540,926.68 2540,950.24 2550.3,960.53 2613.39,960.53 2646.92,927 3055.6,927 3270,1141.4 3320.3,1141.4 3685.94,1507.04 3685.94,1575.32 3741.21,1630.6 3915.32,1630.6 4020.3,1735.58 4020.3,2121.5 v1(4043.1,2144.3) ; v1(4144.88,2145.87) 4144.88,2335.16 4217.69,2407.97 R373.2@4295.58,2407.97 R372.1@4347.35,2407.97 4386.01,2407.97 4406.5,2387.48 U7.19@4421.65,2387.48
  SIGNAL LAYER w6: v1(4043.1,2144.3) 4044.67,2145.87 v1(4144.88,2145.87)
Pin19_3: R380.1 R381.2 R411.1 U13.19 | length 2924
  Top Layer w6: v1(2146.4,2334.84) 2141.14,2340.1 R380.1@2112.52,2340.1 R381.2@2112.52,2380.9 2146.4,2380.9 2163.38,2397.88 2197.97,2397.88 2208.37,2387.48 U13.19@2221.65,2387.48
  Top Layer w12: v2(571.66,885.79) R411.1@571.66,920.35
  SIGNAL LAYER w6: v2(571.66,885.79) 571.66,1456.96 1080,1965.3 1128.8,1965.3 1312.7,2149.2 1312.7,2208.47 1430,2325.77 1430,2423.19 1451.21,2444.4 1735.31,2444.4 1844.87,2334.84 v1(2146.4,2334.84)
Pin19_4: R388.1 R389.2 R416.1 U19.19 | length 2462.6
  Top Layer w6: v1(1011.83,2335) 1031.83,2355 1031.83,2368.75 1063.09,2400 1097.81,2400 1110.36,2387.45 U19.19@1121.63,2387.45
  Top Layer w12: v2(579.76,686.89) R416.1@579.76,721.45
  SIGNAL LAYER w6: v2(579.76,686.89) 511.9,754.75 511.9,1109.2 416,1205.1 318.34,1205.1 281.23,1242.21 281.23,1291.93 301.7,1312.4 375.7,1386.4 375.7,1545.4 1011.83,2181.54 v1(1011.83,2335)
  Bottom Layer w6: R389.2@920.19,2381.86 920.19,2334.02 R388.1@920.87,2333.35 941.52,2333.35 948.72,2326.14 1002.98,2326.14 v1(1011.83,2335)
Pin_18_1: R345.1 R346.2 R355.1 U1.18 | length 3862.1
  Top Layer w6: R355.1@2707.88,401.4 2727.48,421 2783.35,421 2817,454.65 2817,494.77 2858.64,536.41 2859.98,536.41 2860.08,536.5 2983.99,536.5 3023.49,576 3106.41,576 3317.63,787.22 3317.63,787.55 3339.89,809.81 3340.22,809.81 3348.28,817.88 v1(3423.26,817.88) v1@3427.09,817.88 ; R345.1@3246.04,2400 R346.2@3246.04,2449.88 3286.46,2449.88 3299.64,2436.7 v1@3296.94,2434 ; v1(3296,2434) v1@3296.94,2434 ; U1.18@3357.09,2422.91 3313.43,2422.91 3302.35,2434 v1@3296.94,2434
  SIGNAL LAYER w6: v1(3296,2434) 3455.6,2434 3476.5,2413.1 3515.2,2413.1 3549.6,2447.5 3712.47,2447.5 3731.57,2466.6 3762.8,2466.6 3998.1,2231.3 4165.98,2231.3 4225,2172.28 4225,1678 3423.26,876.26 v1(3423.26,817.88)
Pin_19_1: R343.1 R344.2 R356.1 U1.19 | length 3100.2
  Top Layer w6: R356.1@2035.59,503.23 2035.59,536.04 2112.55,613.01 v1(2112.55,697.56) ; v1(3286.84,2405) 3295.03,2405 3312.55,2387.48 U1.19@3321.65,2387.48
  SIGNAL LAYER w6: v1(2112.55,697.56) 2288.9,873.9 2729.9,873.9 2845.2,989.2 3137,989.2 3340.6,1192.8 3340.6,1317.1 3270,1387.7 3270,2152.3 3330,2212.3 3330,2361.84 v1(3286.84,2405)
  Bottom Layer w6: R343.1@3222.01,2448.62 3222.01,2401.61 R344.2@3223.62,2400 3281.84,2400 v1(3286.84,2405)
PoDL_12V_Port_J7: C145.1 R168.2 U10.25 U10.26 | length 1776.4
  SIGNAL/POWER LAYER w15: v2(3663.59,3045.05) 3693.38,3074.84 3782.37,3074.84 3832.36,3024.85 3965.15,3024.85 4066.84,3126.54 4363.13,3126.54 4446.47,3043.2 4713.22,3043.2 4747.9,3077.88 v2(4990.86,3077.88)
  Bottom Layer w15: R168.2@3603.12,3049.13 R168.2@3605.08,3047.17 ; C145.1@3605.08,2991.39 R168.2@3605.08,3047.17 ; v2(3663.59,3045.05) 3661.54,3047.09 3605.16,3047.09 R168.2@3605.08,3047.17 ; v2(4990.86,3077.88) 4994.92,3077.88 5008.68,3064.11 U10.26@5166.69,3064.11 U10.25@5166.69,3038.52
PoDL_12V_Port_J8: C136.1 R183.2 U10.27 U10.28 | length 587.4
  Bottom Layer w15: C136.1@4710.33,2990.49 4710.33,3049.62 R183.2@4710.44,3049.73 4718.32,3049.73 4728.53,3059.94 4728.53,3067.82 4793.5,3132.79 5066.39,3132.79 5083.88,3115.3 U10.28@5166.69,3115.3 U10.27@5166.69,3089.7
PoDL_12V_Port_J9: C146.1 R187.2 U10.17 U10.18 | length 3025.7
  SIGNAL/POWER LAYER w15: v5(2584.15,3060.44) 2637.59,3113.88 3248.18,3113.88 3318.56,3043.5 3580.72,3043.5 3652.75,2971.47 4124.94,2971.47 4176.25,3022.77 4225.95,3022.77 4270.84,2977.87 4551.84,2977.87 4570.72,2958.99 4773.4,2958.99 4831.81,3017.4 5043.87,3017.4 5113.22,2948.04 v5(5113.22,2853.22)
  Bottom Layer w15: C146.1@2506.13,2990.19 2506.13,3043.78 R187.2@2508.66,3046.31 2570.02,3046.31 v5(2584.15,3060.44) ; v5(5113.22,2853.22) 5115.66,2853.22 5121.83,2859.39 U10.18@5166.69,2859.39 U10.17@5166.69,2833.8
PoDL_12V_Port_J10: C147.1 R204.2 U10.15 U10.16 | length 4199.4
  SIGNAL/POWER LAYER w15: v5@1479.59,3051.66 1550.98,3123.06 2158.42,3123.06 2243.59,3037.89 2370.98,3037.89 2400.7,3008.17 2599.17,3008.17 2652.44,3061.44 2835.43,3061.44 2912.27,2984.61 3031.51,2984.61 3060.86,3013.97 3132.26,3013.97 3163.84,2982.39 3401.75,2982.39 3417.44,2966.7 3553.91,2966.7 3602.51,2918.1 4131.67,2918.1 4158.66,2891.1 4236.59,2891.1 4267.39,2921.91 4787.84,2921.91 4845.83,2979.9 5025.6,2979.9 5075.25,2930.24 5075.25,2842.92 v5(5113.22,2804.94)
  Bottom Layer w15: C147.1@1410.77,2985.96 1410.77,3045.35 R204.2@1412.78,3047.35 1475.28,3047.35 v5@1479.59,3051.66 ; v5(5113.22,2804.94) 5116.49,2808.21 U10.16@5166.69,2808.21 U10.15@5166.69,2782.62
  other v5: 1477.43,3049.51
PRG0_MDIO0_MDC: J2.98 R304.2 | length 165.2
  Top Layer w6: v1(1677.19,405.01) 1695,422.82 R304.2@1695,481.38
  Bottom Layer w6: J2.98@1666.54,482.01 1666.85,481.69 1666.85,415.35 v1(1677.19,405.01)
PRG0_MDIO0_MDIO: J2.100 R305.2 | length 125.4
  Top Layer w6: R305.2@1638.98,480 1638.98,427.79 v1(1646.85,419.92)
  Bottom Layer w6: v1(1646.85,419.92) J2.100@1646.85,482.01
PRG1_MDIO0_MDC: J2.54 R302.2 | length 96.1
  Bottom Layer w6: J2.54@2296.46,482.01 2296.46,428.89 2315,410.35 R302.2@2315,393.62
PRG1_MDIO0_MDIO: J2.56 R303.2 | length 91.2
  Bottom Layer w6: R303.2@2270,393.62 2270,438.19 2276.77,444.96 J2.56@2276.77,482.01
PWM_Main: J12.1 R410.2 R415.2
RESET_N1: J20.2 R47.2 R48.1 | length 1390.5
  Top Layer w10: R47.2@3692.76,2140 R48.1@3692.76,2090 3692.76,2041.64 3707.4,2027 3740.83,2027 3849.11,2135.28 v1(3849.11,2155.94)
  SIGNAL/POWER LAYER w10: J20.2@3133.93,2687.13 3220.72,2600.34 3625.01,2600.34 3849.11,2376.24 v1(3849.11,2155.94)
RESET_N2: J21.2 R100.2 R101.1 | length 818.8
  Top Layer w10: R100.2@4772.76,2150 R101.1@4772.76,2100 4772.76,2055.31 v1(4818.07,2010)
  SIGNAL LAYER w10: v1(4818.07,2010) 4837.57,2029.5 4876.7,2029.5 5018.1,1888.1 5327.53,1888.1 J21.2@5386.85,1828.78
RESET_N3: J22.2 R153.2 R154.1 | length 715.6
  Top Layer w10: R153.2@2592.76,2160 R154.1@2592.76,2120 2592.76,2052.18 v1(2607.51,2037.43)
  SIGNAL LAYER w10: v1(2607.51,2037.43) 2637.43,2037.43 2891.92,2291.92 J22.2@2891.92,2489.03
RESET_N4: J23.2 R206.2 R207.1 | length 882.6
  Top Layer w10: v1(1454.47,2023.73) 1462.76,2032.01 R207.1@1462.76,2070 R206.2@1462.76,2120
  Bottom Layer w10: J23.2@1333.7,1341 1418.85,1426.15 1418.85,1554.39 1514.99,1650.52 1514.99,1963.21 v1(1454.47,2023.73)
RESET_N_ALL: J20.1 J21.1 J22.1 J23.1 R1.2 R263.2 | length 8553.1
  Top Layer w10: v2(990,1005.48) 990,996.67 1413.84,572.83 1509.9,572.83 1534.25,597.18 R1.2@1534.25,642.99 ; v1(1580,2041.58) 1611.24,2041.58 v1(1705.71,2136.06) ; J22.1@2891.92,2589.03 2995.14,2589.03 3033.93,2627.83 J20.1@3033.93,2687.13
  SIGNAL LAYER w10: v1(3778.35,1982.99) 3760.67,2000.67 3760.67,2043.79 3837.05,2120.17 3961.92,2120.17 v1(4008,2166.25) ; v1(4833.07,1940) 4833.07,1856.99 4984.06,1706 5285.34,1706 5305,1725.66 5383.74,1725.66 J21.1@5386.85,1728.78
  SIGNAL/POWER LAYER w10: v1(1705.71,2136.06) 1747.79,2136.06 1773.77,2110.09 v1(1895.03,2110.09) ; v1(2648.42,1971.89) 2690,2013.47 2690,2306.69 2819.41,2436.1 2819.41,2516.52 J22.1@2891.92,2589.03 ; v1(2970,2150.22) 2906.99,2150.22 2887.4,2169.82 2887.4,2227.82 2934.58,2275 2974.36,2275 3108.65,2409.29 3108.65,2563.46 3033.93,2638.18 J20.1@3033.93,2687.13
  Bottom Layer w10: R263.2@798.62,479.61 798.62,814.1 v2(990,1005.48) 1225.52,1241 J23.1@1333.7,1241 1447.24,1354.54 1447.24,1536.6 1546.25,1635.6 1546.25,1960.91 1580,1994.66 v1(1580,2041.58) ; v1(1895.03,2110.09) 2035.11,1970 2646.53,1970 v1(2648.42,1971.89) ; v1(2970,2150.22) 3008.58,2150.22 3153,2005.8 3233.3,2005.8 3300.9,2073.4 3434.9,2073.4 3461,2047.3 3461,2021.8 3499.81,1982.99 v1(3778.35,1982.99) ; v1(4008,2166.25) 4008.64,2166.25 4008.64,2147.65 4063.39,2092.9 4081.99,2092.9 4189.89,1985 4788.07,1985 v1(4833.07,1940)
RX_CLK-1: R52.1 R341.1 R342.2 U1.27 | length 254.2
  Top Layer w6: R52.1@3250,2140 3285.99,2140 v1(3305,2159.01) 3305,2174.5 3321.65,2191.15 U1.27@3321.65,2230
  Bottom Layer w6: R341.1@3248.62,2090 3248.62,2138.62 R342.2@3250,2140 3285.99,2140 v1(3305,2159.01)
RX_CLK-2: R105.1 R370.1 R371.2 U7.27 | length 220.9
  Top Layer w6: R105.1@4350,2150 4374.38,2150 v1(4398.63,2174.25) 4421.65,2197.28 U7.27@4421.65,2230
  Bottom Layer w6: R370.1@4396.02,2078.42 R371.2@4396.02,2127.38 4396.02,2171.64 v1(4398.63,2174.25)
RX_CLK-3: R158.1 R378.1 R379.2 U13.27 | length 405.1
  Top Layer w6: R158.1@2140,2140 2140.7,2140.7 v1(2161.6,2140.7) 2201.81,2180.9 2201.81,2218.7 2213.1,2230 U13.27@2221.65,2230
  Bottom Layer w6: R378.1@1909.76,2170.14 R379.2@1966.38,2170.14 1995.82,2140.7 v1(2161.6,2140.7)
RX_CLK-4: R211.1 R386.1 R387.2 U19.27 | length 513.6
  Top Layer w6: R211.1@1030,2140 v1(1057.17,2140) 1121.65,2204.49 U19.27@1121.65,2230
  Bottom Layer w6: R386.1@709.27,2173.44 764.61,2173.44 R387.2@765.45,2174.29 765.45,2161.8 787.24,2140 v1(1057.17,2140)
RX_CTRL-1: R35.1 R36.2 R53.1 U1.15 | length 674.1
  Top Layer w6: R53.1@3298,2592.91 3298,2572 v1(3324.75,2545.25) 3324.75,2520.55 3375.78,2469.53 3389.57,2469.53 3416.14,2442.96 U1.15@3416.14,2422.91
  Bottom Layer w6: R35.1@3000,2350 R36.2@3052.76,2350 3075.51,2372.76 3117.76,2372.76 3125.75,2380.75 3125.75,2380.97 3125.75,2384.05 3125.75,2451.57 3146.17,2472 3198,2472 3271.25,2545.25 v1(3324.75,2545.25)
RX_CTRL-2: R88.1 R89.2 R106.1 U7.15 | length 661.5
  Top Layer w6: R106.1@4395.94,2586.38 4416.11,2566.21 4416.11,2529.2 4475.78,2469.53 4486.47,2469.53 4516.14,2439.86 U7.15@4516.14,2422.91
  Bottom Layer w6: R88.1@4077.24,2360 R89.2@4130,2360 4152,2382 4208.28,2382 4208.48,2381.8 4241,2381.8 4337.72,2478.52 4337.72,2499.76 4360.63,2522.68 4360.63,2532.91 4391.23,2563.51 v1(4416.32,2563.51)
RX_CTRL-3: R141.1 R142.2 R159.1 U13.15 | length 684
  Top Layer w6: R159.1@2120,2470 2151.88,2470 v1(2161.88,2460) 2178.78,2476.9 2278.4,2476.9 2316.14,2439.16 U13.15@2316.14,2422.91
  Bottom Layer w6: R142.2@1960,2380 1961.65,2380 2007.93,2426.28 2007.93,2459.02 2025.27,2476.35 2025.27,2522.03 2059.53,2556.29 2084,2556.29 2100.98,2539.3 2100.98,2485.73 2126.72,2460 v1(2161.88,2460)
  Bottom Layer w10: R141.1@1907.24,2380 R142.2@1960,2380
RX_CTRL-4: R194.1 R195.2 R212.1 U19.15 | length 700.8
  Top Layer w6: R212.1@1020,2470 1058.28,2470 1065.08,2463.2 1079.56,2477.68 1175.15,2477.68 1216.14,2436.69 U19.15@1216.14,2422.91
  Bottom Layer w6: R194.1@710,2380 R195.2@760,2380 781.81,2401.81 825,2401.81 825,2403.11 834,2412.11 834,2440.38 872,2478.38 872,2492.74 902.64,2523.38 923.35,2523.38 983.53,2463.2 v1(1065.01,2463.2)
RX_D0-1: R29.1 R30.2 R54.1 U1.26 | length 408
  Top Layer w6: R54.1@3250,2180 3255,2185 v1(3270,2185) 3279.38,2185 3299.84,2205.46 3299.84,2236.18 3313.35,2249.68 U1.26@3321.65,2249.68
  Bottom Layer w6: R29.1@3000,2200 R30.2@3052.76,2200 3074.57,2178.19 3272.57,2178.19 3270,2180.76 v1(3270,2185)
RX_D0-2: R82.1 R83.2 R107.1 U7.26 | length 450.3
  Top Layer w6: R107.1@4350,2190 v1(4374.38,2190) 4397.21,2212.83 4397.21,2240 4406.9,2249.68 U7.26@4421.65,2249.68
  Bottom Layer w6: R82.1@4077.24,2210 R83.2@4130,2210
  Bottom Layer w8: R83.2@4130,2210 4130,2197.53 4168.03,2159.5 4343.05,2159.5 4373.55,2190 v1(4374.38,2190)
RX_D0-3: R135.1 R136.2 R160.1 U13.26 | length 402.5
  Top Layer w6: R160.1@2140,2180 v1(2164.38,2180) 2188.81,2204.43 2188.81,2224.09 2199.69,2234.97 2199.69,2238.7 2210.67,2249.68 U13.26@2221.65,2249.68
  Bottom Layer w6: R136.2@1962.76,2224 1990.01,2196.75 2084.33,2196.75 2101.08,2180 v1(2164.38,2180) ; R136.2@1962.76,2230 R136.2@1968.42,2230
  Bottom Layer w10: R135.1@1910,2224 R136.2@1962.76,2224
RX_D0-4: R188.1 R189.2 R213.1 U19.26 | length 495.4
  Top Layer w6: R213.1@1030,2180 v1(1054.38,2180) 1092.76,2218.38 1092.76,2232.76 1109.69,2249.68 U19.26@1121.65,2249.68
  Bottom Layer w6: R188.1@708.62,2230 R189.2@762.76,2230 791.38,2201.38 870.55,2201.38 891.93,2180 v1(1054.38,2180)
RX_D1-1: R31.1 R32.2 R55.1 U1.25 | length 409.3
  Top Layer w6: R55.1@3250,2220 v1(3274.38,2220) 3286.84,2232.46 3286.84,2252 3304.21,2269.37 U1.25@3321.65,2269.37
  Bottom Layer w6: R31.1@3000,2250 R32.2@3052.76,2250 3075.62,2272.86 3161.31,2272.86 3214.17,2220 v1(3274.38,2220)
RX_D1-2: R84.1 R85.2 R108.1 U7.25 | length 429.1
  Top Layer w6: R108.1@4350,2230 4371.4,2230 v1(4374.4,2227) 4374.4,2238.3 4405.47,2269.37 U7.25@4421.65,2269.37
  Bottom Layer w6: R84.1@4077.24,2260 R85.2@4130,2260 4131.97,2260 4157.56,2285.59 4232.79,2285.59 4291.38,2227 v1(4374.4,2227)
RX_D1-3: R137.1 R138.2 R161.1 U13.25 | length 383.2
  Top Layer w6: R161.1@2140,2220 v1(2164.38,2220) 2186.69,2242.31 2186.69,2245.46 2210.6,2269.37 U13.25@2221.65,2269.37
  Bottom Layer w6: R138.2@1960,2280 1985,2255 2043.24,2255 2078.24,2220 v1(2164.38,2220)
  Bottom Layer w10: R137.1@1910,2280 R138.2@1960,2280
RX_D1-4: R190.1 R191.2 R214.1 U19.25 | length 485.1
  Top Layer w6: R214.1@1030,2220 v1(1054.38,2220) 1103.75,2269.37 U19.25@1121.65,2269.37
  Bottom Layer w6: R190.1@710,2280 R191.2@760,2280 788.19,2251.81 843.13,2251.81 879.43,2215.5 1049.88,2215.5 v1(1054.38,2220)
RX_D2-1: R33.1 R34.2 R56.1 U1.24 | length 392.4
  Top Layer w6: R56.1@3250,2260 3260,2270 v1(3274.38,2270) 3293.43,2289.05 U1.24@3321.65,2289.05
  Bottom Layer w6: R33.1@3000,2300 R34.2@3052.76,2300 3052.76,2300.6 3078.17,2326.01 3170,2326.01 3226.01,2270 v1(3274.38,2270)
RX_D2-2: R86.1 R87.2 R109.1 U7.24 | length 400.7
  Top Layer w6: R109.1@4350,2270 4357.17,2270 v1(4367.17,2280) 4376.22,2289.05 U7.24@4421.65,2289.05
  Bottom Layer w6: R86.1@4077.24,2310 R87.2@4130,2310 4152.69,2332.68 4219.18,2332.68 4271.87,2280 v1(4367.17,2280)
RX_D2-3: R139.1 R140.2 R162.1 U13.24 | length 379.8
  Top Layer w6: R162.1@2140,2260 v1(2164.38,2260) 2181.47,2260 2210.53,2289.05 U13.24@2221.65,2289.05
  Bottom Layer w6: R140.2@1960,2330 1961.18,2330 1982.83,2308.35 1987.2,2308.35 1987.35,2308.19 2032.93,2308.19 2081.12,2260 v1(2164.38,2260)
  Bottom Layer w10: R139.1@1907.24,2330 R140.2@1960,2330
RX_D2-4: R192.1 R193.2 R215.1 U19.24 | length 508.7
  Top Layer w6: R215.1@1030,2260 v1(1054.38,2260) 1083.43,2289.05 U19.24@1121.65,2289.05
  Bottom Layer w6: R192.1@710,2330 R193.2@760,2330 781.81,2308.19 840.1,2308.19 860,2288.28 860,2259.5 877.33,2242.16 964.07,2242.16 981.91,2260 v1(1054.38,2260)
RX_D3-1: R57.1 U1.23 | length 75.3
  Top Layer w6: R57.1@3250,2300 3275.74,2300 3284.48,2308.74 U1.23@3321.65,2308.74
RX_D3-2: R110.1 U7.23 | length 124.2
  Top Layer w6: R110.1@4303.82,2312.5 4332.5,2312.5 4342.07,2302.93 4401.93,2302.93 4407.74,2308.74 U7.23@4421.65,2308.74
RX_D3-3: R163.1 U13.23 | length 85.3
  Top Layer w6: R163.1@2140,2300 2159.5,2300 2168.24,2308.74 U13.23@2221.65,2308.74
RX_D3-4: R216.1 U19.23 | length 95.3
  Top Layer w6: R216.1@1030,2300 1038.74,2308.74 U19.23@1121.65,2308.74
Sel1/2: J70.2 R324.2 U40.1 U41.1 | length 590.9
  Top Layer w12: U41.1@5348.69,2033.9 5318.5,2033.9 5309.05,2043.34 5309.05,2248.69 5335.19,2274.83 U40.1@5348.69,2274.83 5348.69,2249.84 5374.98,2223.55 5475.73,2223.55 R324.2@5511.48,2187.79 5512.27,2187.01 5588.07,2187.01 J70.2@5588.86,2186.22
Sel3/4: J73.2 R98.2 U42.1 U43.1 | length 647.2
  Top Layer w12: U43.1@544.74,2214.91 519.12,2214.91 500.61,2233.41 500.61,2404.91 534,2438.3 534,2490.43 535.88,2492.31 U42.1@544.74,2492.31 576.59,2492.31 591.22,2477.68 650,2477.68 671.22,2498.9 671.22,2544.12 678.25,2551.15 699.19,2551.15 705,2556.96 R98.2@705,2560.9 J73.2@705,2644.38
STRP1-1: J19.8 R400.2 | length 100.4
  Top Layer w10: R400.2@219.16,821.45 J19.8@319.53,821.45
STRP-1: R37.1 R38.2 R361.1 R400.1 U1.14 | length 5958.8
  Top Layer w6: v1(3428.5,2460) 3435.83,2452.68 U1.14@3435.83,2422.91
  Top Layer w12: v2(171.91,786.89) R400.1@171.91,821.45
  SIGNAL/POWER LAYER w6: v2(171.91,786.89) 109.3,849.5 109.3,1144.9 355.5,1391.1 355.5,1931.03 259.82,2026.71 259.82,2700.52 452.91,2893.61 672.61,2893.61 832.24,2733.98 874.21,2733.98 887.83,2747.59 1207.29,2747.59 1236.95,2717.94 1289.78,2717.94 1312.86,2741.02 1517.56,2741.02 1659.23,2599.35 2808.32,2599.35 2869.16,2660.2 2928,2660.2 3000,2588.2 v1(3000,2443.21)
  Bottom Layer w6: v1(3000,2443.21) R37.1@3000,2400 R38.2@3052.76,2400 3052.76,2443.21 3104.55,2495 3182.21,2495 3257.21,2570 3348.28,2570 3360,2558.28 3360,2541.38 R361.1@3382.48,2518.9 3428.5,2472.87 v1(3428.5,2460)
STRP-2: R90.1 R91.2 R365.1 R404.1 U7.14 | length 740
  Top Layer w6: v1(4529.33,2455.16) 4535.83,2448.66 U7.14@4535.83,2422.91
  Top Layer w8: R404.1@4027.33,2447.77 v2(4077.24,2447.77)
  Bottom Layer w8: v2(4077.24,2447.77) R90.1@4077.24,2410 R91.2@4130,2410 4130,2413 4171.41,2454.41 4292.5,2454.41 4323.72,2485.63 4323.72,2505.56 4346.63,2528.47 4346.63,2538.71 4392.43,2584.51 4434.2,2584.51 R365.1@4493.11,2525.59 4493.11,2499.02 4529.33,2462.8 v1(4529.33,2455.16)
STRP-3: R143.1 R144.2 R409.1 U13.14 | length 686.7
  Top Layer w6: R409.1@2125,2577.79 v1(2125,2505) 2135.21,2494.79 2283.31,2494.79 2335.83,2442.27 U13.14@2335.83,2422.91
  Bottom Layer w10: R143.1@1907.22,2437.5 1942.38,2437.5 1949.09,2430.79 R144.2@1965.79,2430.79 1992.93,2457.93 1992.93,2469.21 2010.27,2486.55 2010.27,2528.24 2053.31,2571.29 2093.71,2571.29 2125,2540 v1(2125,2505)
STRP-4: R196.1 R197.2 R414.1 U19.14 | length 739.3
  Top Layer w6: v1(1004.5,2503.34) 1001.87,2505.97 R414.1@1001.87,2551.41 1052.69,2551.41 1111.26,2492.84 1185.25,2492.84 1235.83,2442.27 U19.14@1235.83,2422.91
  Bottom Layer w6: R196.1@710,2430 R197.2@760,2430 760,2485 787.28,2512.28 856.02,2512.28 888.74,2545 956.97,2545 998.63,2503.34 v1(1004.5,2503.34)
"SYNC OUT IEP0 ICSSG1": J2.24 R351.2 | length 3084.5
  Top Layer w25: v2(5180,924.34) 5181.38,925.72 R351.2@5233.23,925.72
  SIGNAL LAYER w20: v1(2880.86,570) 2880.86,613.83 2960.69,693.67
  SIGNAL LAYER w25: 2960.69,693.67 2960.69,694.63 3009.86,743.8 3369.5,743.8 3546.8,566.5 4306,566.5 4472.76,733.26 5075.46,733.26 5145.6,803.4 5145.6,889.94 v2(5180,924.34)
  Bottom Layer w10: J2.24@2591.73,482.01 2591.73,542.51 2619.22,570 v1(2880.86,570)
"SYNC OUT IEP1": J2.36 R353.2 | length 3441
  Top Layer w25: v2(5176.8,1286.9) R353.2@5233.23,1286.9
  SIGNAL LAYER w25: v1(2469.52,430.8) 2469.52,447.62 2641.72,619.82 2641.72,653.72 2697.78,709.78 2733.06,709.78 2837.78,814.5 3344.05,814.5 3446.85,711.7 3681.7,711.7 3749.5,643.9 4177.1,643.9 4355.95,822.75 4606.58,822.75 4652.43,868.6 4910.42,868.6 5014.4,972.58 5014.4,1124.5 v2(5176.8,1286.9)
  Bottom Layer w8: v1(2469.52,430.8) 2469.52,430.01 2473.62,425.9 J2.36@2473.62,482.01
TRD1_N: C137.2 R221.2 U1.13 | length 200.4
  Top Layer w4: C137.2@3391.73,2495.28 3391.73,2499.21 3421.81,2529.29 3428.5,2529.29 R221.2@3441.73,2542.52 3459.35,2524.9 3459.35,2440.57 3455.51,2436.72 U1.13@3455.51,2422.91
TRD1_P: C138.1 R222.2 U1.12 | length 201.5
  Top Layer w4: U1.12@3475.2,2422.91 3475.2,2436.72 3471.35,2440.57 3471.35,2522.14 R222.2@3491.73,2542.52 3517.32,2516.93 3524.02,2516.93 3541.73,2499.21 C138.1@3541.73,2495.28
TRD1A_N: L1.4 R221.1 R223.1 U25.1 | length 352.2
  Top Layer w4: R223.1@3391.73,2642.52 3441.73,2592.52 R221.1@3441.73,2589.76 3460.73,2608.76 3460.73,2656.83 3444.41,2673.15 U25.1@3444.41,2681.42 3444.41,2690.11 3464,2709.7 3464,2724.72 3450,2738.72 L1.4@3450,2839.92
TRD1A_P: L1.1 R222.1 R224.2 U25.2 | length 354.6
  Top Layer w4: L1.1@3489.37,2839.92 3489.37,2738.09 3476,2724.72 3476,2709.1 3495.59,2689.51 U25.2@3495.59,2681.42 3495.59,2674.19 3472.73,2651.33 3472.73,2608.76 R222.1@3491.73,2589.76 3493.73,2591.76 3493.73,2594.52 R224.2@3541.73,2642.52
TRD1B_N: C141.2 L1.3 | length 88.2
  Top Layer w4: C141.2@3440.87,3027.76 3464.55,3004.07 3464.55,2977.18 3450.87,2963.5 L1.3@3450.87,2955
TRD1B_P: C142.2 L1.2 | length 88.5
  Top Layer w4: L1.2@3490.24,2955 3490.24,2964.63 3476.55,2978.31 3476.55,3003.44 C142.2@3500.87,3027.76
TRD1C_N: C141.1 D33.1 J7.2 L25.4 R226.2 | length 464.1
  Top Layer w4: J7.2@3439.13,3290 3464,3265.13 3464,3164 D33.1@3440,3140 3464,3116 3464,3094 C141.1@3440,3070
  Bottom Layer w15: L25.4@3407.9,3194.51 3418.06,3194.51 3433.2,3209.65 3433.2,3284.07 J7.2@3439.13,3290 3439.13,3358.09 R226.2@3423.94,3373.28
TRD1C_P: C142.1 D34.2 J7.1 L25.1 R225.2 | length 459.1
  Top Layer w4: C142.1@3500,3070 3476,3094 3476,3116 D34.2@3500,3140 3476,3164 3476,3256.5 3509.5,3290 J7.1@3510,3290
  Bottom Layer w15: R225.2@3514.26,3373.28 3498.25,3357.27 3498.25,3301.75 3521.09,3278.91 L25.1@3521.09,3194.51
TRD2_N: C148.2 R232.2 U7.13 | length 198.1
  Top Layer w4: C148.2@4491.73,2495.27 4493.73,2497.27 4496.49,2497.27 R232.2@4541.73,2542.52 4559.35,2524.9 4559.35,2440.57 4555.51,2436.72 U7.13@4555.51,2422.91
TRD2_P: C149.1 R233.2 U7.12 | length 199.2
  Top Layer w4: U7.12@4575.2,2422.91 4575.2,2436.72 4571.35,2440.57 4571.35,2522.14 R233.2@4591.73,2542.52 4636.98,2497.27 4639.73,2497.27 C149.1@4641.73,2495.27
TRD2A_N: L2.4 R232.1 R234.1 U26.1 | length 357.9
  Top Layer w4: R234.1@4491.73,2642.52 4539.73,2594.52 4539.73,2591.76 R232.1@4541.73,2589.76 4560.73,2608.76 4560.73,2656.83 4544.41,2673.15 4544.41,2690.11 4564,2709.7 4564,2723.46 4550,2737.46 L2.4@4550,2839.92 ; U26.1@4540,2681.42 U26.1@4544.04,2677.38
TRD2A_P: L2.1 R233.1 R235.2 U26.2 | length 351.9
  Top Layer w4: L2.1@4589.37,2839.92 4589.37,2736.82 4576,2723.45 4576,2709.1 4595.59,2689.51 4595.59,2674.19 4572.73,2651.33 4572.73,2608.76 R233.1@4591.73,2589.76 R235.2@4641.73,2639.76
TRD2B_N: C152.2 L2.3 | length 88.2
  Top Layer w4: C152.2@4540,3032.76 4563.69,3009.07 4563.69,2982.18 4550,2968.5 L2.3@4550,2960
TRD2B_P: C153.2 L2.2 | length 88.5
  Top Layer w4: L2.2@4589.37,2960 4589.37,2969.63 4575.69,2983.31 4575.69,3008.44 C153.2@4600,3032.76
